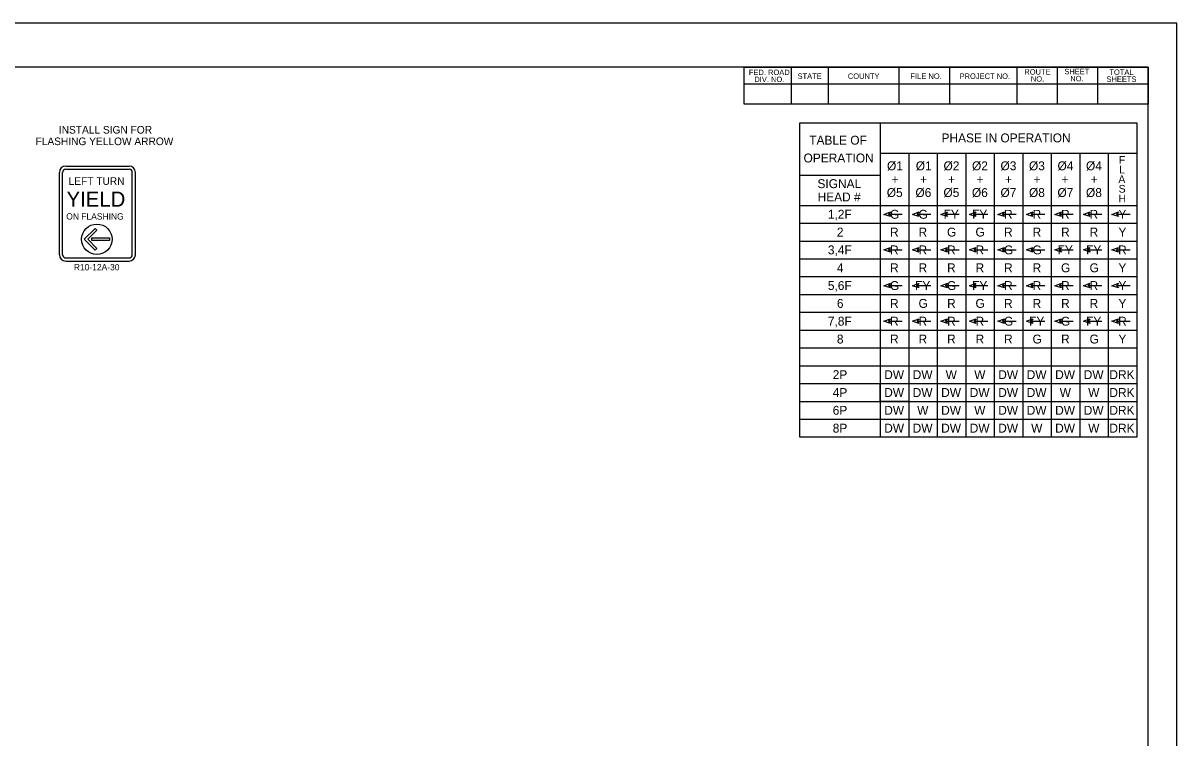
# Model space of a CAD drawing. Extents: x 0 to 3.01, y -0.05 to 1.83.
# Drawn here: x 1.481 to 3, y 0.892 to 1.833 of the extents above; entities that cross this region are included whole.
import ezdxf

# ---------------------------------------------------------------- set-up
doc = ezdxf.new("R2010")
doc.units = 0
for name, color, linetype in [('Default', 7, 'Continuous'), ('RD_SHT_IplotShp', 7, 'Continuous'), ('TR_TS_Border', 7, 'Continuous'), ('TR_TS_PD_Signs', 7, 'Continuous'), ('TR_TS_Phase1', 7, 'Continuous'), ('TR_TS_Phase1-5', 7, 'Continuous'), ('TR_TS_Phase2', 7, 'Continuous'), ('TR_TS_Phase3', 7, 'Continuous'), ('TR_TS_Phase4', 7, 'Continuous'), ('TR_TS_Phase5', 7, 'Continuous'), ('TR_TS_Phase6', 7, 'Continuous'), ('TR_TS_Phase7', 7, 'Continuous'), ('TR_TS_Phase8', 7, 'Continuous'), ('TR_TS_Text', 7, 'Continuous')]:
    doc.layers.add(name, color=color, linetype=linetype)

msp = doc.modelspace()

# ---------------------------------------------------------------- linework, layer by layer
at = {"layer": 'Default'}
for p, q in [((2.6094, 1.702), (2.6094, 1.2885)), ((2.6094, 1.6623), (2.9471, 1.6623)), ((2.6469, 1.6623), (2.6469, 1.2885)), ((2.6844, 1.6623), (2.6844, 1.2885)), ((2.7219, 1.6623), (2.7219, 1.2885)), ((2.7595, 1.6623), (2.7595, 1.2885)), ((2.797, 1.6623), (2.797, 1.2885)), ((2.8345, 1.6623), (2.8345, 1.2885)), ((2.8721, 1.6623), (2.8721, 1.2885)), ((2.9096, 1.6623), (2.9096, 1.2885)), ((2.5035, 1.633), (2.6094, 1.633)), ((2.5035, 1.5934), (2.9471, 1.5934)), ((2.5035, 1.5699), (2.9471, 1.5699)), ((2.5035, 1.5465), (2.9471, 1.5465)), ((2.5035, 1.523), (2.9471, 1.523)), ((2.5035, 1.4996), (2.9471, 1.4996)), ((2.5035, 1.4761), (2.9471, 1.4761)), ((2.5035, 1.4527), (2.9471, 1.4527)), ((2.5035, 1.4292), (2.9471, 1.4292)), ((2.5035, 1.4058), (2.9471, 1.4058)), ((2.5035, 1.3823), (2.9471, 1.3823)), ((2.5035, 1.3588), (2.9471, 1.3588)), ((2.5035, 1.3354), (2.9471, 1.3354)), ((2.5035, 1.3119), (2.9471, 1.3119))]:
    msp.add_line(p, q, dxfattribs=at)
for points in [[(2.5035, 1.702), (2.9471, 1.702), (2.9471, 1.2885), (2.5035, 1.2885)], [(2.6094, 1.3588), (2.6469, 1.3588), (2.6469, 1.3354), (2.6094, 1.3354)]]:
    msp.add_lwpolyline(points, close=True, dxfattribs=at)
at = {"layer": 'RD_SHT_IplotShp'}
msp.add_lwpolyline([(0, 0), (3, 0), (3, 1.8333), (0, 1.8333)], close=True, dxfattribs=at)
at = {"layer": 'TR_TS_Border'}
for p, q in [((2.9419, 1.8333), (0.031, 1.8333)), ((3, 0), (3, 1.8333)), ((2.9623, 1.7754), (0.1686, 1.7754)), ((2.4925, 1.7266), (2.4925, 1.7754)), ((2.5412, 1.7266), (2.5412, 1.7754)), ((2.6343, 1.7266), (2.6343, 1.7754)), ((2.7008, 1.7266), (2.7008, 1.7754)), ((2.7895, 1.7266), (2.7895, 1.7754)), ((2.8427, 1.7266), (2.8427, 1.7754)), ((2.8959, 1.7266), (2.8959, 1.7754)), ((2.9623, 0.0475), (2.9623, 1.7754)), ((2.4304, 1.7532), (2.9623, 1.7532))]:
    msp.add_line(p, q, dxfattribs=at)
msp.add_lwpolyline([(2.9623, 1.7754), (2.9623, 1.7266), (2.4304, 1.7266), (2.4304, 1.7754)], close=True, dxfattribs=at)
at = {"layer": 'TR_TS_PD_Signs'}
for p, q in [((1.537, 1.6451), (1.6204, 1.6451)), ((1.537, 1.641), (1.6204, 1.641)), ((1.5287, 1.5284), (1.5287, 1.6368)), ((1.5328, 1.5284), (1.5328, 1.6368)), ((1.6246, 1.5284), (1.6246, 1.6368)), ((1.6288, 1.5284), (1.6288, 1.6368)), ((1.5612, 1.5488), (1.5755, 1.5631)), ((1.5779, 1.5608), (1.5659, 1.5488)), ((1.5755, 1.5631), (1.5779, 1.5608)), ((1.5755, 1.5345), (1.5612, 1.5488)), ((1.5659, 1.5488), (1.5779, 1.5368)), ((1.5779, 1.5368), (1.5755, 1.5345)), ((1.537, 1.5242), (1.6204, 1.5242)), ((1.537, 1.52), (1.6204, 1.52))]:
    msp.add_line(p, q, dxfattribs=at)
msp.add_lwpolyline([(1.5712, 1.5505), (1.5946, 1.5505), (1.5946, 1.5471), (1.5712, 1.5471), (1.5712, 1.5505)], dxfattribs=at)
msp.add_circle((1.5779, 1.5488), 0.02, dxfattribs=at)
for centre, radius, start, end in [((1.537, 1.6368), 0.00834, 90, 180), ((1.537, 1.6368), 0.00417, 90, 180), ((1.6204, 1.6368), 0.00834, 360, 90), ((1.6204, 1.6368), 0.00417, 360, 90), ((1.537, 1.5284), 0.00834, 180, 270), ((1.537, 1.5284), 0.00417, 180, 270), ((1.6204, 1.5284), 0.00417, 270, 360), ((1.6204, 1.5284), 0.00834, 270, 360)]:
    msp.add_arc(centre, radius, start, end, dxfattribs=at)
at = {"layer": 'TR_TS_Phase1'}
for p, q in [((2.6203, 1.5817), (2.6383, 1.5817)), ((2.6579, 1.5817), (2.6758, 1.5817)), ((2.6954, 1.5817), (2.7133, 1.5817)), ((2.7329, 1.5817), (2.7509, 1.5817)), ((2.7704, 1.5817), (2.7884, 1.5817)), ((2.808, 1.5817), (2.8259, 1.5817)), ((2.8455, 1.5817), (2.8635, 1.5817)), ((2.883, 1.5817), (2.901, 1.5817)), ((2.9206, 1.5817), (2.9385, 1.5817))]:
    msp.add_line(p, q, dxfattribs=at)
for points in [[(2.6229, 1.5786), (2.6142, 1.5816), (2.6228, 1.5848), (2.6203, 1.5817)], [(2.6604, 1.5786), (2.6518, 1.5816), (2.6603, 1.5848), (2.6579, 1.5817)], [(2.6979, 1.5786), (2.6893, 1.5816), (2.6978, 1.5848), (2.6954, 1.5817)], [(2.7354, 1.5786), (2.7268, 1.5816), (2.7354, 1.5848), (2.7329, 1.5817)], [(2.773, 1.5786), (2.7644, 1.5816), (2.7729, 1.5848), (2.7704, 1.5817)], [(2.8105, 1.5786), (2.8019, 1.5816), (2.8104, 1.5848), (2.808, 1.5817)], [(2.848, 1.5786), (2.8394, 1.5816), (2.848, 1.5848), (2.8455, 1.5817)], [(2.8856, 1.5786), (2.8769, 1.5816), (2.8855, 1.5848), (2.883, 1.5817)], [(2.9231, 1.5786), (2.9145, 1.5816), (2.923, 1.5848), (2.9206, 1.5817)]]:
    msp.add_lwpolyline(points, close=True, dxfattribs=at)
at = {"layer": 'TR_TS_Phase3'}
for p, q in [((2.6203, 1.5348), (2.6383, 1.5348)), ((2.6579, 1.5348), (2.6758, 1.5348)), ((2.6954, 1.5348), (2.7133, 1.5348)), ((2.7329, 1.5348), (2.7509, 1.5348)), ((2.7704, 1.5348), (2.7884, 1.5348)), ((2.808, 1.5348), (2.8259, 1.5348)), ((2.8455, 1.5348), (2.8635, 1.5348)), ((2.883, 1.5348), (2.901, 1.5348)), ((2.9206, 1.5348), (2.9385, 1.5348))]:
    msp.add_line(p, q, dxfattribs=at)
for points in [[(2.6229, 1.5317), (2.6142, 1.5347), (2.6228, 1.5379), (2.6203, 1.5348)], [(2.6604, 1.5317), (2.6518, 1.5347), (2.6603, 1.5379), (2.6579, 1.5348)], [(2.6979, 1.5317), (2.6893, 1.5347), (2.6978, 1.5379), (2.6954, 1.5348)], [(2.7354, 1.5317), (2.7268, 1.5347), (2.7354, 1.5379), (2.7329, 1.5348)], [(2.773, 1.5317), (2.7644, 1.5347), (2.7729, 1.5379), (2.7704, 1.5348)], [(2.8105, 1.5317), (2.8019, 1.5347), (2.8104, 1.5379), (2.808, 1.5348)], [(2.848, 1.5317), (2.8394, 1.5347), (2.848, 1.5379), (2.8455, 1.5348)], [(2.8856, 1.5317), (2.8769, 1.5347), (2.8855, 1.5379), (2.883, 1.5348)], [(2.9231, 1.5317), (2.9145, 1.5347), (2.923, 1.5379), (2.9206, 1.5348)]]:
    msp.add_lwpolyline(points, close=True, dxfattribs=at)
at = {"layer": 'TR_TS_Phase5'}
for p, q in [((2.6203, 1.4879), (2.6383, 1.4879)), ((2.6579, 1.4879), (2.6758, 1.4879)), ((2.6954, 1.4879), (2.7133, 1.4879)), ((2.7329, 1.4879), (2.7509, 1.4879)), ((2.7704, 1.4879), (2.7884, 1.4879)), ((2.808, 1.4879), (2.8259, 1.4879)), ((2.8455, 1.4879), (2.8635, 1.4879)), ((2.883, 1.4879), (2.901, 1.4879)), ((2.9206, 1.4879), (2.9385, 1.4879))]:
    msp.add_line(p, q, dxfattribs=at)
for points in [[(2.6229, 1.4848), (2.6142, 1.4877), (2.6228, 1.491), (2.6203, 1.4879)], [(2.6604, 1.4848), (2.6518, 1.4877), (2.6603, 1.491), (2.6579, 1.4879)], [(2.6979, 1.4848), (2.6893, 1.4877), (2.6978, 1.491), (2.6954, 1.4879)], [(2.7354, 1.4848), (2.7268, 1.4877), (2.7354, 1.491), (2.7329, 1.4879)], [(2.773, 1.4848), (2.7644, 1.4877), (2.7729, 1.491), (2.7704, 1.4879)], [(2.8105, 1.4848), (2.8019, 1.4877), (2.8104, 1.491), (2.808, 1.4879)], [(2.848, 1.4848), (2.8394, 1.4877), (2.848, 1.491), (2.8455, 1.4879)], [(2.8856, 1.4848), (2.8769, 1.4877), (2.8855, 1.491), (2.883, 1.4879)], [(2.9231, 1.4848), (2.9145, 1.4877), (2.923, 1.491), (2.9206, 1.4879)]]:
    msp.add_lwpolyline(points, close=True, dxfattribs=at)
at = {"layer": 'TR_TS_Phase7'}
for p, q in [((2.6203, 1.4409), (2.6383, 1.4409)), ((2.6579, 1.4409), (2.6758, 1.4409)), ((2.6954, 1.4409), (2.7133, 1.4409)), ((2.7329, 1.4409), (2.7509, 1.4409)), ((2.7704, 1.4409), (2.7884, 1.4409)), ((2.808, 1.4409), (2.8259, 1.4409)), ((2.8455, 1.4409), (2.8635, 1.4409)), ((2.883, 1.4409), (2.901, 1.4409)), ((2.9206, 1.4409), (2.9385, 1.4409))]:
    msp.add_line(p, q, dxfattribs=at)
for points in [[(2.6229, 1.4379), (2.6142, 1.4408), (2.6228, 1.4441), (2.6203, 1.4409)], [(2.6604, 1.4379), (2.6518, 1.4408), (2.6603, 1.4441), (2.6579, 1.4409)], [(2.6979, 1.4379), (2.6893, 1.4408), (2.6978, 1.4441), (2.6954, 1.4409)], [(2.7354, 1.4379), (2.7268, 1.4408), (2.7354, 1.4441), (2.7329, 1.4409)], [(2.773, 1.4379), (2.7644, 1.4408), (2.7729, 1.4441), (2.7704, 1.4409)], [(2.8105, 1.4379), (2.8019, 1.4408), (2.8104, 1.4441), (2.808, 1.4409)], [(2.848, 1.4379), (2.8394, 1.4408), (2.848, 1.4441), (2.8455, 1.4409)], [(2.8856, 1.4379), (2.8769, 1.4408), (2.8855, 1.4441), (2.883, 1.4409)], [(2.9231, 1.4379), (2.9145, 1.4408), (2.923, 1.4441), (2.9206, 1.4409)]]:
    msp.add_lwpolyline(points, close=True, dxfattribs=at)

# ---------------------------------------------------------------- texts
at = {"layer": 'Default'}
for s, height, p in [('PHASE IN OPERATION', 0.011728, (2.6901, 1.6763)), ('TABLE OF ', 0.01173, (2.5159, 1.6733)), ('OPERATION', 0.01173, (2.5084, 1.6499)), ('F', 0.0102, (2.9237, 1.6482)), ('L', 0.0102, (2.9241, 1.6355)), ('SIGNAL ', 0.01173, (2.5267, 1.6161)), ('A', 0.0102, (2.9229, 1.6228)), ('S', 0.0102, (2.9233, 1.6101)), ('HEAD #', 0.01173, (2.5269, 1.5986)), ('H', 0.0102, (2.9231, 1.5974)), ('2P', 0.01173, (2.5468, 1.3647)), ('DW', 0.01173, (2.6146, 1.3647)), ('DW', 0.01173, (2.6521, 1.3647)), ('W', 0.0117, (2.6955, 1.3647)), ('W', 0.0117, (2.7331, 1.3647)), ('DW', 0.01173, (2.7647, 1.3647)), ('DW', 0.01173, (2.8022, 1.3647)), ('DW', 0.01173, (2.8397, 1.3647)), ('DW', 0.01173, (2.8773, 1.3647)), ('DRK', 0.01173, (2.9111, 1.3647)), ('4P', 0.01173, (2.5468, 1.3412)), ('DW', 0.01173, (2.6146, 1.3412)), ('DW', 0.01173, (2.6521, 1.3412)), ('DW', 0.01173, (2.6896, 1.3412)), ('DW', 0.01173, (2.7272, 1.3412)), ('DW', 0.01173, (2.7647, 1.3412)), ('DW', 0.01173, (2.8022, 1.3412)), ('W', 0.0117, (2.8457, 1.3412)), ('W', 0.0117, (2.8832, 1.3412)), ('DRK', 0.01173, (2.9111, 1.3412)), ('6P', 0.01173, (2.5468, 1.3178)), ('DW', 0.01173, (2.6146, 1.3178)), ('W', 0.0117, (2.658, 1.3178)), ('DW', 0.01173, (2.6896, 1.3178)), ('W', 0.0117, (2.7331, 1.3178)), ('DW', 0.01173, (2.7647, 1.3178)), ('DW', 0.01173, (2.8022, 1.3178)), ('DW', 0.01173, (2.8397, 1.3178)), ('DW', 0.01173, (2.8773, 1.3178)), ('DRK', 0.01173, (2.9111, 1.3178)), ('8P', 0.01173, (2.5468, 1.2943)), ('DW', 0.01173, (2.6146, 1.2943)), ('DW', 0.01173, (2.6521, 1.2943)), ('DW', 0.01173, (2.6896, 1.2943)), ('DW', 0.01173, (2.7272, 1.2943)), ('DW', 0.01173, (2.7647, 1.2943)), ('W', 0.0117, (2.8081, 1.2943)), ('DW', 0.01173, (2.8397, 1.2943)), ('W', 0.0117, (2.8832, 1.2943)), ('DRK', 0.01173, (2.9111, 1.2943))]:
    msp.add_text(s, height=height, rotation=360, dxfattribs=at).set_placement(p)
at = {"layer": 'TR_TS_Border'}
for s, height, p in [('FED. ROAD', 0.00715, (2.4364, 1.7649)), ('DIV. NO.', 0.00715, (2.4436, 1.7557)), ('STATE', 0.00715, (2.5005, 1.7599)), ('COUNTY', 0.00715, (2.5667, 1.7599)), ('FILE NO.', 0.00715, (2.6492, 1.7599)), ('PROJECT NO.', 0.007148, (2.7139, 1.7599)), ('ROUTE', 0.00715, (2.7991, 1.7655)), ('NO.', 0.00715, (2.8077, 1.7563)), ('SHEET', 0.00715, (2.8518, 1.766)), ('NO.', 0.00715, (2.8596, 1.7567)), ('SHEETS', 0.00715, (2.9072, 1.7559)), ('TOTAL', 0.00715, (2.9111, 1.7651))]:
    msp.add_text(s, height=height, dxfattribs=at).set_placement(p)
at = {"layer": 'TR_TS_PD_Signs'}
for s, height, p in [('LEFT TURN', 0.01001, (1.5407, 1.6204)), ('YIELD', 0.02002, (1.538, 1.5916)), ('ON FLASHING', 0.00834, (1.5376, 1.5747))]:
    msp.add_text(s, height=height, rotation=360, dxfattribs=at).set_placement(p)
at = {"layer": 'TR_TS_Phase1'}
for s, height, p in [('Ø1', 0.01173, (2.6183, 1.6396)), ('Ø1', 0.01173, (2.6562, 1.6396)), ('1,2F', 0.01173, (2.5404, 1.5758)), ('G', 0.0117, (2.6223, 1.5758)), ('G', 0.0117, (2.6598, 1.5758)), ('FY', 0.01173, (2.6928, 1.5758)), ('FY', 0.01173, (2.7303, 1.5758)), ('R', 0.0117, (2.7724, 1.5758)), ('R', 0.0117, (2.81, 1.5758)), ('R', 0.0117, (2.8475, 1.5758)), ('R', 0.0117, (2.885, 1.5758)), ('Y', 0.0117, (2.923, 1.5758))]:
    msp.add_text(s, height=height, rotation=360, dxfattribs=at).set_placement(p)
at = {"layer": 'TR_TS_Phase1-5'}
for p in [(2.6243, 1.622), (2.6618, 1.622), (2.6987, 1.622), (2.7362, 1.622), (2.7737, 1.622), (2.8112, 1.622), (2.8481, 1.622), (2.8865, 1.622)]:
    msp.add_text('+', height=0.0117, rotation=360, dxfattribs=at).set_placement(p)
at = {"layer": 'TR_TS_Phase2'}
for s, height, p in [('Ø2', 0.01173, (2.6927, 1.6396)), ('Ø2', 0.01173, (2.7302, 1.6396)), ('2', 0.0117, (2.5523, 1.5524)), ('R', 0.0117, (2.6223, 1.5524)), ('R', 0.0117, (2.6598, 1.5524)), ('G', 0.0117, (2.6973, 1.5524)), ('G', 0.0117, (2.7348, 1.5524)), ('R', 0.0117, (2.7724, 1.5524)), ('R', 0.0117, (2.81, 1.5524)), ('R', 0.0117, (2.8475, 1.5524)), ('R', 0.0117, (2.885, 1.5524)), ('Y', 0.0117, (2.923, 1.5524))]:
    msp.add_text(s, height=height, rotation=360, dxfattribs=at).set_placement(p)
at = {"layer": 'TR_TS_Phase3'}
for s, height, p in [('Ø3', 0.01173, (2.7677, 1.6396)), ('Ø3', 0.01173, (2.8052, 1.6396)), ('3,4F', 0.01173, (2.5404, 1.5289)), ('R', 0.0117, (2.6223, 1.5289)), ('R', 0.0117, (2.6598, 1.5289)), ('R', 0.0117, (2.6974, 1.5289)), ('R', 0.0117, (2.7349, 1.5289)), ('G', 0.0117, (2.7724, 1.5289)), ('G', 0.0117, (2.8099, 1.5289)), ('FY', 0.01173, (2.8429, 1.5289)), ('FY', 0.01173, (2.8804, 1.5289)), ('R', 0.0117, (2.9226, 1.5289))]:
    msp.add_text(s, height=height, rotation=360, dxfattribs=at).set_placement(p)
at = {"layer": 'TR_TS_Phase4'}
for s, height, p in [('Ø4', 0.01173, (2.8428, 1.6396)), ('Ø4', 0.01173, (2.8803, 1.6396)), ('4', 0.0117, (2.5523, 1.5054)), ('R', 0.0117, (2.6223, 1.5054)), ('R', 0.0117, (2.6598, 1.5054)), ('R', 0.0117, (2.6974, 1.5054)), ('R', 0.0117, (2.7349, 1.5054)), ('R', 0.0117, (2.7724, 1.5054)), ('R', 0.0117, (2.81, 1.5054)), ('G', 0.0117, (2.8474, 1.5054)), ('G', 0.0117, (2.885, 1.5054)), ('Y', 0.0117, (2.923, 1.5054))]:
    msp.add_text(s, height=height, rotation=360, dxfattribs=at).set_placement(p)
at = {"layer": 'TR_TS_Phase5'}
for s, height, p in [('Ø5', 0.01173, (2.618, 1.6044)), ('Ø5', 0.01173, (2.6926, 1.6044)), ('5,6F', 0.01173, (2.5404, 1.482)), ('G', 0.0117, (2.6223, 1.482)), ('FY', 0.01173, (2.6552, 1.482)), ('G', 0.0117, (2.6973, 1.482)), ('FY', 0.01173, (2.7303, 1.482)), ('R', 0.0117, (2.7724, 1.482)), ('R', 0.0117, (2.81, 1.482)), ('R', 0.0117, (2.8475, 1.482)), ('R', 0.0117, (2.885, 1.482)), ('Y', 0.0117, (2.923, 1.482))]:
    msp.add_text(s, height=height, rotation=360, dxfattribs=at).set_placement(p)
at = {"layer": 'TR_TS_Phase6'}
for s, height, p in [('Ø6', 0.01173, (2.6557, 1.6044)), ('Ø6', 0.01173, (2.7301, 1.6044)), ('6', 0.0117, (2.5523, 1.4585)), ('R', 0.0117, (2.6223, 1.4585)), ('G', 0.0117, (2.6598, 1.4585)), ('R', 0.0117, (2.6974, 1.4585)), ('G', 0.0117, (2.7348, 1.4585)), ('R', 0.0117, (2.7724, 1.4585)), ('R', 0.0117, (2.81, 1.4585)), ('R', 0.0117, (2.8475, 1.4585)), ('R', 0.0117, (2.885, 1.4585)), ('Y', 0.0117, (2.923, 1.4585))]:
    msp.add_text(s, height=height, rotation=360, dxfattribs=at).set_placement(p)
at = {"layer": 'TR_TS_Phase7'}
for s, height, p in [('Ø7', 0.01173, (2.7677, 1.6044)), ('Ø7', 0.01173, (2.8427, 1.6044)), ('7,8F', 0.01173, (2.5404, 1.4351)), ('R', 0.0117, (2.6223, 1.4351)), ('R', 0.0117, (2.6598, 1.4351)), ('R', 0.0117, (2.6974, 1.4351)), ('R', 0.0117, (2.7349, 1.4351)), ('G', 0.0117, (2.7724, 1.4351)), ('FY', 0.01173, (2.8054, 1.4351)), ('G', 0.0117, (2.8474, 1.4351)), ('FY', 0.01173, (2.8804, 1.4351)), ('R', 0.0117, (2.9226, 1.4351))]:
    msp.add_text(s, height=height, rotation=360, dxfattribs=at).set_placement(p)
at = {"layer": 'TR_TS_Phase8'}
for s, height, p in [('Ø8', 0.01173, (2.8052, 1.6044)), ('Ø8', 0.01173, (2.8803, 1.6044)), ('8', 0.0117, (2.5523, 1.4116)), ('R', 0.0117, (2.6223, 1.4116)), ('R', 0.0117, (2.6598, 1.4116)), ('R', 0.0117, (2.6974, 1.4116)), ('R', 0.0117, (2.7349, 1.4116)), ('R', 0.0117, (2.7724, 1.4116)), ('G', 0.0117, (2.8099, 1.4116)), ('R', 0.0117, (2.8475, 1.4116)), ('G', 0.0117, (2.885, 1.4116)), ('Y', 0.0117, (2.923, 1.4116))]:
    msp.add_text(s, height=height, rotation=360, dxfattribs=at).set_placement(p)
at = {"layer": 'TR_TS_Text'}
for s, height, p in [('INSTALL SIGN FOR ', 0.010008, (1.5279, 1.6879)), ('FLASHING YELLOW ARROW', 0.010008, (1.4972, 1.6727)), ('R10-12A-30', 0.00834, (1.5476, 1.5079))]:
    msp.add_text(s, height=height, rotation=360, dxfattribs=at).set_placement(p)

doc.saveas('drawing.dxf')
